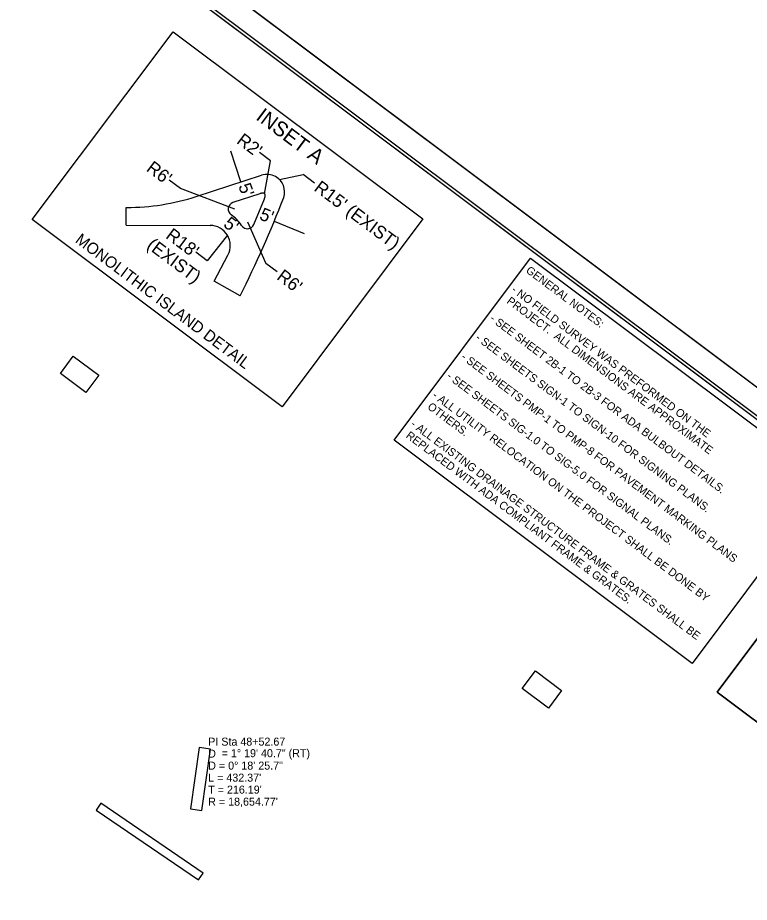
# Model space of a CAD drawing. Extents: x 928111 to 937215, y 684180 to 686530.
# Drawn here: x 931236 to 931876, y 684839 to 685613 of the extents above; entities that cross this region are included whole.
import ezdxf

# ---------------------------------------------------------------- set-up
doc = ezdxf.new("R2010")
doc.units = 0
for name, color, linetype in [('Default', 7, 'Continuous'), ('Exist Horizontal Alignment Curve and Spiral Data', 7, 'Continuous'), ('Old_Level_4', 7, 'Continuous'), ('Prop Conc 4in Sidewalk', 7, 'Continuous'), ('Prop Dimension', 7, 'Continuous'), ('Prop Dimension Text', 7, 'Continuous'), ('Prop DSN Text', 7, 'Continuous'), ('Sheet Cutting Line CELL', 7, 'Continuous'), ('Sheet Plan CELL', 7, 'Continuous'), ('Sheet Plan Layout CELL', 7, 'Continuous'), ('Sheet Plot Border Inside CELL', 7, 'Continuous'), ('Sheet Plot Border Outside CELL', 7, 'Continuous')]:
    doc.layers.add(name, color=color, linetype=linetype)

msp = doc.modelspace()

# ---------------------------------------------------------------- linework, layer by layer
at = {"layer": 'Default'}
for p, q in [((931392.56, 685456.31), (931449.6, 685474.89)), ((931448.03, 685458.6), (931424.55, 685450.95)), ((931442.79, 685431.77), (931452.1, 685454.2)), ((931331.35, 685446.68), (931331.74, 685446.68)), ((931331.3, 685431.21), (931404.67, 685430.97)), ((931408.27, 685382.25), (931420.27, 685405.05)), ((931431.01, 685369.48), (931408.27, 685382.25))]:
    msp.add_line(p, q, dxfattribs=at)
for centre, radius, start, end in [((931454.34, 685460.35), 15.29, 60.3796, 108.04891), ((931331.97, 685642.25), 195.57, 269.93247, 288.04892), ((931331.97, 685642.25), 195.57, 269.93247, 288.04892), ((931426.41, 685445.25), 6, 108.04892, 235.70964), ((931404.62, 685413.29), 32.69, 32.48654, 55.70964), ((931404.62, 685413.29), 17.69, 332.23503, 89.81915), ((931437.25, 685434.07), 6, 212.48654, 337.46537)]:
    msp.add_arc(centre, radius, start, end, dxfattribs=at)
msp.add_spline([(931452.1, 685454.2), (931452.2, 685454.45), (931452.3, 685454.7), (931452.38, 685454.93), (931452.47, 685455.17), (931452.54, 685455.39), (931452.61, 685455.61), (931452.67, 685455.82), (931452.72, 685456.03), (931452.76, 685456.23), (931452.8, 685456.42), (931452.83, 685456.61), (931452.86, 685456.79), (931452.88, 685456.96), (931452.89, 685457.13), (931452.89, 685457.29), (931452.89, 685457.44), (931452.87, 685457.59), (931452.86, 685457.73), (931452.83, 685457.86), (931452.8, 685457.99), (931452.76, 685458.11), (931452.71, 685458.22), (931452.66, 685458.33), (931452.6, 685458.43), (931452.53, 685458.53), (931452.46, 685458.61), (931452.37, 685458.7), (931452.29, 685458.77), (931452.19, 685458.84), (931452.09, 685458.9), (931451.98, 685458.96), (931451.86, 685459), (931451.73, 685459.05), (931451.6, 685459.08), (931451.46, 685459.11), (931451.32, 685459.13), (931451.17, 685459.15), (931451.01, 685459.16), (931450.84, 685459.16), (931450.67, 685459.16), (931450.48, 685459.15), (931450.3, 685459.13), (931450.1, 685459.11), (931449.9, 685459.08), (931449.69, 685459.04), (931449.47, 685459), (931449.25, 685458.95), (931449.02, 685458.89), (931448.78, 685458.83), (931448.54, 685458.76), (931448.29, 685458.69), (931448.03, 685458.6)], degree=3, dxfattribs=at)
at = {"layer": 'Old_Level_4'}
for centre, radius, start, end in [((931454.52, 685460.25), 15.29, 341.11331, 61.16086), ((930556.86, 685807.58), 977.79, 333.38118, 338.88284)]:
    msp.add_arc(centre, radius, start, end, dxfattribs=at)
at = {"layer": 'Prop Conc 4in Sidewalk'}
msp.add_line((931331.3, 685431.21), (931331.35, 685446.68), dxfattribs=at)
at = {"layer": 'Prop Dimension'}
for p, q in [((931431.48, 685468.99), (931422.74, 685495.8)), ((931457.61, 685487.38), (931447.73, 685494.79)), ((931452.36, 685458.53), (931457.61, 685487.38)), ((931465.31, 685471.05), (931486.16, 685475.36)), ((931496.05, 685467.95), (931486.16, 685475.36)), ((931378.67, 685463.13), (931368.78, 685470.53)), ((931426.41, 685445.25), (931378.67, 685463.13)), ((931437.25, 685434.07), (931453.48, 685397.78)), ((931460.74, 685434.65), (931486.81, 685423.89)), ((931419.77, 685422.4), (931402.14, 685400.06)), ((931402.14, 685400.06), (931392.25, 685407.47)), ((931463.37, 685390.37), (931453.48, 685397.78))]:
    msp.add_line(p, q, dxfattribs=at)
at = {"layer": 'Prop DSN Text'}
for points in [[(931372.3, 685600.37), (931590.77, 685436.67), (931467.61, 685272.31), (931249.14, 685436)], [(931684.84, 685402.44), (931945.48, 685207.14), (931826.18, 685047.92), (931565.53, 685243.22)], [(931285.04, 685316.47), (931307.21, 685299.86), (931295.85, 685284.71), (931273.69, 685301.32)], [(931689.12, 685041.29), (931711.97, 685024.17), (931700.47, 685008.83), (931677.62, 685025.94)], [(931397.54, 684919.22), (931405.08, 684972.83), (931395.02, 684974.25), (931387.48, 684920.63)], [(931305.15, 684919.56), (931394.6, 684858.56), (931398.67, 684864.52), (931309.22, 684925.53)]]:
    msp.add_lwpolyline(points, close=True, dxfattribs=at)
at = {"layer": 'Sheet Cutting Line CELL'}
msp.add_line((932193.6, 685056.42), (930846.34, 686065.9), dxfattribs=at)
at = {"layer": 'Sheet Plan CELL'}
for points in [[(932166.53, 685048.6), (930966.09, 685948.07), (930336.47, 685107.79), (931536.89, 684208.33)], [(931848.22, 685022.84), (932039.7, 684879.36), (932166.54, 685048.59), (931975.03, 685192.08)]]:
    msp.add_lwpolyline(points, close=True, dxfattribs=at)
at = {"layer": 'Sheet Plan Layout CELL'}
msp.add_lwpolyline([(930966.05, 685948.07), (930336.47, 685107.79), (931536.88, 684208.33), (932039.68, 684879.37), (931848.22, 685022.84), (931975.03, 685192.08)], close=True, dxfattribs=at)
at = {"layer": 'Sheet Plot Border Inside CELL'}
msp.add_lwpolyline([(930212.13, 685197.81), (931545.39, 684198.84), (932178, 685043.11), (930844.75, 686042.1)], close=True, dxfattribs=at)
at = {"layer": 'Sheet Plot Border Outside CELL'}
msp.add_lwpolyline([(930189.74, 685189.6), (931537, 684180.12), (932193.6, 685056.42), (930846.34, 686065.9)], close=True, dxfattribs=at)

# ---------------------------------------------------------------- texts
at = {"layer": 'Exist Horizontal Alignment Curve and Spiral Data'}
for s, p in [('PI Sta 48+52.67', (931403, 684976)), ('D', (931403, 684965.5)), ('= 1%%d 19\' 40.7" (RT)', (931414.77, 684965.89)), ('D = 0%%d 18\' 25.7"', (931403, 684955)), ("L = 432.37'", (931403, 684944.5)), ("T = 216.19'", (931403, 684934)), ("R = 18,654.77'", (931403, 684923.5))]:
    msp.add_text(s, height=7, dxfattribs=at).set_placement(p)
at = {"layer": 'Prop Dimension'}
for s, p in [("R18'", (931365.07, 685420.44)), ('(EXIST)', (931348.46, 685411.8))]:
    msp.add_text(s, height=11.25, rotation=323.15623, dxfattribs=at).set_placement(p)
at = {"layer": 'Prop Dimension Text'}
for s, rotation, p in [("R2'", 323.15623, (931427.06, 685503.44)), ("R6'", 323.15623, (931348.12, 685479.19)), ("5'", 290.81202, (931429.15, 685465.44)), ("R15' (EXIST)", 323.15623, (931494.77, 685462.02)), ("5'", 337.57955, (931446.96, 685436.56)), ("5'", 323.15623, (931415.53, 685430.53)), ("R6'", 323.15623, (931462.15, 685384.39))]:
    msp.add_text(s, height=11.25, rotation=rotation, dxfattribs=at).set_placement(p)
at = {"layer": 'Prop DSN Text'}
for s, height, p in [('INSET A', 13, (931443.91, 685524.19)), ('MONOLITHIC ISLAND DETAIL', 10, (931285.96, 685416.73)), ('GENERAL NOTES:', 7, (931680.24, 685390.33)), ('- NO FIELD SURVEY WAS PREFORMED ON THE ', 7, (931667.65, 685373.52)), (' PROJECT.  ALL DIMENSIONS ARE APPROXIMATE', 7, (931661.35, 685365.12)), ('- SEE SHEET 2B-1 TO 2B-3 FOR ADA BULBOUT DETAILS.', 7, (931648.76, 685348.31)), ('- SEE SHEETS SIGN-1 TO SIGN-10 FOR SIGNING PLANS.', 7, (931636.17, 685331.51)), ('- SEE SHEETS PMP-1 TO PMP-8 FOR PAVEMENT MARKING PLANS  ', 7, (931623.57, 685314.7)), ('- SEE SHEETS SIG-1.0 TO SIG-5.0 FOR SIGNAL PLANS.', 7, (931610.98, 685297.9)), ('- ALL UTILITY RELOCATION ON THE PROJECT SHALL BE DONE BY ', 7, (931598.39, 685281.09)), (' OTHERS.', 7, (931592.09, 685272.69)), ('- ALL EXISTING DRAINAGE STRUCTURE FRAME & GRATES SHALL BE ', 7, (931579.5, 685255.88)), (' REPLACED WITH ADA COMPLIANT FRAME & GRATES.', 7, (931573.2, 685247.48))]:
    msp.add_text(s, height=height, rotation=323.15623, dxfattribs=at).set_placement(p)

doc.saveas('drawing.dxf')
